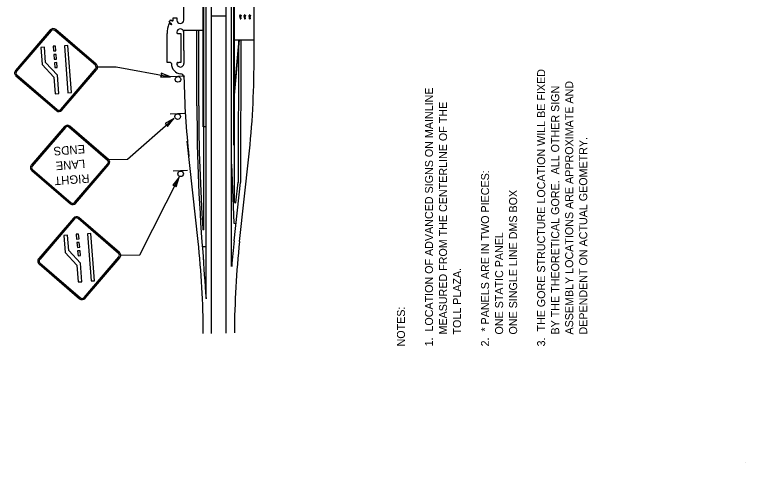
# Model space of a CAD drawing. Extents: x -102308 to -98250, y 54554 to 62383.
# Drawn here: x -101443 to -98250, y 54554 to 56510 of the extents above; entities that cross this region are included whole.
import ezdxf

# ---------------------------------------------------------------- set-up
doc = ezdxf.new("R2010")
doc.units = 0
for name, color, linetype in [('AdhocPoint_dp', 7, 'Continuous'), ('LeaderLine_dp', 7, 'Continuous'), ('RoadwayMisc', 7, 'Continuous'), ('SignPanel', 7, 'Continuous'), ('SignSupport', 7, 'Continuous'), ('TextNotes', 7, 'Continuous')]:
    doc.layers.add(name, color=color, linetype=linetype)

msp = doc.modelspace()

# ---------------------------------------------------------------- linework, layer by layer
at = {"layer": 'AdhocPoint_dp'}
msp.add_line((-98250.2, 54553.9), (-98250.2, 54553.9), dxfattribs=at)
at = {"layer": 'LeaderLine_dp'}
for p, q in [((-101082.8, 56281.7), (-100999.4, 56282.5)), ((-100999.4, 56282.5), (-100761.4, 56238.2)), ((-100800.9, 56245.5), (-100805.6, 56238.2)), ((-100805.6, 56238.2), (-100761.4, 56238.2)), ((-100761.4, 56238.2), (-100802.6, 56254.4)), ((-100802.6, 56254.4), (-100800.9, 56245.5)), ((-100949.7, 55878.4), (-100747.2, 56056.5)), ((-100747.2, 56056.5), (-100785.4, 56034.1)), ((-100774.5, 56021.7), (-100747.2, 56056.5)), ((-100785.4, 56034.1), (-100777.4, 56030)), ((-100777.4, 56030), (-100774.5, 56021.7)), ((-101033.1, 55877.6), (-100949.7, 55878.4)), ((-100896.3, 55460.1), (-100724.4, 55800.5)), ((-100724.4, 55800.5), (-100751.5, 55765.5)), ((-100736.8, 55758), (-100724.4, 55800.5)), ((-100751.5, 55765.5), (-100742.5, 55764.6)), ((-100742.5, 55764.6), (-100736.8, 55758)), ((-100979.6, 55459.3), (-100896.3, 55460.1))]:
    msp.add_line(p, q, dxfattribs=at)
at = {"layer": 'RoadwayMisc'}
for p, q in [((-100582.8, 55117.4), (-100582.8, 62374)), ((-100518.8, 55119.1), (-100518.8, 62374)), ((-100494.8, 55409.7), (-100494.8, 57849.7)), ((-100484.8, 55939.6), (-100484.8, 57219.6)), ((-100482.8, 55689), (-100482.8, 57219.6)), ((-100618.8, 56019.6), (-100618.8, 57119.6)), ((-100616.8, 56019.6), (-100616.8, 57119.6)), ((-100606.8, 56019.6), (-100606.8, 57119.6)), ((-100704.4, 56486.1), (-100704.4, 56804.6)), ((-100397.1, 56304.6), (-100397.1, 56804.6)), ((-100749.7, 56485.6), (-100749.7, 56496.9)), ((-100749.7, 56496.9), (-100749.7, 56496.9)), ((-100749.7, 56496.9), (-100733.7, 56496.9)), ((-100733.7, 56496.9), (-100733.7, 56496.9)), ((-100733.7, 56496.9), (-100733.7, 56486.1)), ((-100582.8, 56504.6), (-100518.8, 56504.6)), ((-100459.6, 56508), (-100452.8, 56508)), ((-100459.6, 56508), (-100459.6, 56506)), ((-100457.2, 56496), (-100459.6, 56506)), ((-100457.8, 56509.6), (-100458.8, 56509.6)), ((-100458.8, 56509.6), (-100458.8, 56508.6)), ((-100458.8, 56508.6), (-100457.8, 56508.6)), ((-100458.2, 56496), (-100458.2, 56492.5)), ((-100458.2, 56496), (-100457.2, 56496)), ((-100457.8, 56508.6), (-100457.8, 56509.6)), ((-100457.2, 56496), (-100457.2, 56492.5)), ((-100457.2, 56496), (-100455.2, 56496)), ((-100457.2, 56492.5), (-100455.2, 56492.5)), ((-100455.2, 56496), (-100452.8, 56506)), ((-100455.2, 56496), (-100455.2, 56492.5)), ((-100454.2, 56496), (-100455.2, 56496)), ((-100454.2, 56496), (-100454.2, 56492.5)), ((-100452.8, 56508), (-100452.8, 56506)), ((-100440.8, 56508), (-100434, 56508)), ((-100440.8, 56508), (-100440.8, 56506)), ((-100438.4, 56496), (-100440.8, 56506)), ((-100439, 56509.6), (-100440, 56509.6)), ((-100440, 56509.6), (-100440, 56508.6)), ((-100440, 56508.6), (-100439, 56508.6)), ((-100439.4, 56496), (-100438.4, 56496)), ((-100439.4, 56496), (-100439.4, 56492.5)), ((-100439, 56508.6), (-100439, 56509.6)), ((-100438.4, 56496), (-100438.4, 56492.5)), ((-100438.4, 56496), (-100436.4, 56496)), ((-100438.4, 56492.5), (-100436.4, 56492.5)), ((-100436.4, 56496), (-100434, 56506)), ((-100436.4, 56496), (-100436.4, 56492.5)), ((-100435.4, 56496), (-100436.4, 56496)), ((-100435.4, 56496), (-100435.4, 56492.5)), ((-100434, 56508), (-100434, 56506)), ((-100419, 56508), (-100412.2, 56508)), ((-100419, 56508), (-100419, 56506)), ((-100416.6, 56496), (-100419, 56506)), ((-100417.2, 56509.6), (-100418.2, 56509.6)), ((-100418.2, 56509.6), (-100418.2, 56508.6)), ((-100418.2, 56508.6), (-100417.2, 56508.6)), ((-100417.6, 56496), (-100417.6, 56492.5)), ((-100417.6, 56496), (-100416.6, 56496)), ((-100417.2, 56508.6), (-100417.2, 56509.6)), ((-100416.6, 56496), (-100416.6, 56492.5)), ((-100416.6, 56496), (-100414.6, 56496)), ((-100416.6, 56492.5), (-100414.6, 56492.5)), ((-100414.6, 56496), (-100412.2, 56506)), ((-100413.6, 56496), (-100414.6, 56496)), ((-100414.6, 56496), (-100414.6, 56492.5)), ((-100413.6, 56496), (-100413.6, 56492.5)), ((-100412.2, 56508), (-100412.2, 56506)), ((-100704.4, 56353.3), (-100704.4, 56441)), ((-100618.8, 56441), (-100704.4, 56441)), ((-100646.7, 56111.2), (-100646.7, 56441)), ((-100638.7, 56111.2), (-100638.7, 56441)), ((-100482.8, 56400.6), (-100462.3, 56400.6)), ((-100482.8, 56180), (-100462.3, 56400.6)), ((-100482.8, 56158.3), (-100460.3, 56400.6)), ((-100464.5, 56400.7), (-100466.2, 55777.1)), ((-100460.3, 56400.6), (-100397.1, 56400.6)), ((-100454.5, 56400.7), (-100456.2, 55777)), ((-100763.4, 56301.1), (-100768.9, 56301.1)), ((-100729.4, 56301.1), (-100726.3, 56301.1)), ((-100616.8, 56019.6), (-100618.8, 56019.6)), ((-100606.8, 56019.6), (-100618.8, 56019.6)), ((-100616.8, 55570.6), (-100616.8, 56019.6)), ((-100606.8, 55269.4), (-100606.8, 56019.6)), ((-100640.9, 55519.7), (-100688.7, 55956.7)), ((-100484.7, 55939.6), (-100482.7, 55939.6)), ((-100460.2, 55519.6), (-100419.7, 55889.6)), ((-100494.8, 55857.6), (-100485.7, 55599.1)), ((-100494.8, 55840.2), (-100494.1, 55839.4)), ((-100484, 55522.2), (-100456.2, 55777)), ((-100475.9, 55688.3), (-100466.1, 55778.1)), ((-100482.8, 55689), (-100475.9, 55688.3)), ((-100485.7, 55599.1), (-100475.8, 55598)), ((-100616.8, 55570.6), (-100620.4, 55570.6)), ((-100606.8, 55495.6), (-100623, 55495.6))]:
    msp.add_line(p, q, dxfattribs=at)
for points in [[(-100757.2, 56469), (-100767.9, 56477), (-100767.9, 56477), (-100760, 56487.4), (-100760, 56487.4), (-100754.5, 56483.2)], [(-100769.9, 56470.8), (-100758.1, 56467.2)], [(-100776.4, 56301.1), (-100776.4, 56301.1), (-100776.4, 56427.1)], [(-100729.7, 56427.1), (-100716.4, 56427.1), (-100716.4, 56301.1), (-100726.3, 56301.1)], [(-100768.9, 56301.1), (-100776.4, 56301.1)]]:
    msp.add_lwpolyline(points, dxfattribs=at)
for centre, radius, start, end in [((-100752.7, 56485.6), 3, 233.0709, 0.0008), ((-100718.7, 56486.1), 15, 180, 267.2045), ((-100719.4, 56486.1), 15, 269.9986, 359.9981), ((-100626.4, 56427.1), 150, 163.0703, 179.9985), ((-100757.8, 56468.2), 1, 253.0525, 53.063), ((-100729.7, 56432.1), 5, 160.5302, 270), ((-100719.4, 56432.7), 15, 359.9989, 176.5954), ((-98794.4, 56353.2), 1910, 179.9968, 181.7147), ((-100763.4, 56296.1), 5, 359.9881, 89.9954), ((-100714.4, 56296.1), 44, 179.995, 265.6625), ((-100729.4, 56296.1), 5, 89.9925, 179.9951), ((-100719, 56296.6), 15.4, 181.7192, 1.7209), ((-96884.7, 56304.6), 3819.2, 180, 180.1138), ((-104216.8, 56304.6), 3819.7, 353.7628, 360), ((-100718.8, 56237.3), 15, 1.0063, 85.6625), ((-96884.7, 56304.6), 3819.2, 181.0063, 186.2372), ((-92646.7, 56111.2), 8000, 179.99992, 184.87894), ((-92646.7, 56111.2), 7992, 179.99992, 183.87996), ((-104438.5, 55104.6), 3819.7, 0.1778, 6.2372), ((-96663.1, 55104.6), 3843.7, 173.7628, 175.4472), ((-96663.1, 55104.6), 3819.7, 173.7628, 179.7687), ((-86274.8, 56389.3), 14375.7, 183.63987, 184.46998)]:
    msp.add_arc(centre, radius, start, end, dxfattribs=at)
at = {"layer": 'SignPanel'}
for p, q in [((-101287.2, 56443.2), (-101439.1, 56266.2)), ((-101283, 56439.6), (-101434.9, 56262.6)), ((-101090.3, 56288.9), (-101267.3, 56440.8)), ((-101086.7, 56293.1), (-101263.7, 56445)), ((-101312.6, 56367.9), (-101328.7, 56366.7)), ((-101328.7, 56366.7), (-101323.1, 56293)), ((-101307.5, 56301.2), (-101312.6, 56367.9)), ((-101264.8, 56373.1), (-101275.1, 56372.2)), ((-101275.1, 56372.2), (-101273.4, 56351.4)), ((-101263, 56352.3), (-101264.8, 56373.1)), ((-101211, 56375.7), (-101225.7, 56374.6)), ((-101225.7, 56374.6), (-101210, 56168.2)), ((-101195.3, 56169.4), (-101211, 56375.7)), ((-101273.4, 56351.4), (-101263, 56352.3)), ((-101261.7, 56336.7), (-101272.1, 56335.9)), ((-101272.1, 56335.9), (-101270.3, 56315.1)), ((-101259.9, 56316), (-101261.7, 56336.7)), ((-101323.1, 56293), (-101271.9, 56237.7)), ((-101256.3, 56245.9), (-101307.5, 56301.2)), ((-101270.3, 56315.1), (-101259.9, 56316)), ((-101258.6, 56300.4), (-101269, 56299.5)), ((-101269, 56299.5), (-101267.2, 56278.8)), ((-101256.9, 56279.7), (-101258.6, 56300.4)), ((-101267.2, 56278.8), (-101256.9, 56279.7)), ((-101241, 56096.2), (-101089.1, 56273.2)), ((-101236.8, 56092.5), (-101084.9, 56269.6)), ((-101437.4, 56242.7), (-101260.3, 56090.8)), ((-101433.7, 56246.9), (-101256.7, 56095)), ((-101271.9, 56237.7), (-101266.2, 56163.9)), ((-101250.1, 56165.2), (-101256.3, 56245.9)), ((-101266.2, 56163.9), (-101250.1, 56165.2)), ((-101210, 56168.2), (-101195.3, 56169.4)), ((-101225, 56021.2), (-101370.3, 55851.8)), ((-101220.9, 56017.8), (-101366.3, 55848.4)), ((-101036.6, 55873.5), (-101206, 56018.9)), ((-101033.1, 55877.6), (-101202.5, 56022.9)), ((-101180.8, 55689.1), (-101035.4, 55858.5)), ((-101176.8, 55685.7), (-101031.4, 55855.1)), ((-101368.6, 55829.3), (-101199.2, 55684)), ((-101365.2, 55833.4), (-101195.8, 55688)), ((-100985.5, 55471.4), (-101162.5, 55623.4)), ((-101186, 55621.6), (-101338, 55444.5)), ((-101181.8, 55617.9), (-101333.7, 55440.9)), ((-100989.1, 55467.2), (-101166.1, 55619.1)), ((-101211.4, 55546.3), (-101227.5, 55545)), ((-101227.5, 55545), (-101221.9, 55471.3)), ((-101206.3, 55479.5), (-101211.4, 55546.3)), ((-101163.6, 55551.4), (-101174, 55550.5)), ((-101174, 55550.5), (-101172.2, 55529.7)), ((-101172.2, 55529.7), (-101161.8, 55530.6)), ((-101161.8, 55530.6), (-101163.6, 55551.4)), ((-101109.8, 55554), (-101124.6, 55552.9)), ((-101124.6, 55552.9), (-101108.8, 55346.6)), ((-101094.1, 55347.7), (-101109.8, 55554)), ((-101160.5, 55515), (-101170.9, 55514.2)), ((-101170.9, 55514.2), (-101169.1, 55493.4)), ((-101169.1, 55493.4), (-101158.7, 55494.3)), ((-101158.7, 55494.3), (-101160.5, 55515)), ((-101221.9, 55471.3), (-101170.7, 55416)), ((-101155.1, 55424.2), (-101206.3, 55479.5)), ((-101157.4, 55478.7), (-101167.8, 55477.8)), ((-101167.8, 55477.8), (-101166.1, 55457.1)), ((-101155.7, 55458), (-101157.4, 55478.7)), ((-101166.1, 55457.1), (-101155.7, 55458)), ((-101139.8, 55274.5), (-100987.9, 55451.5)), ((-101135.6, 55270.9), (-100983.7, 55447.9)), ((-101336.2, 55421), (-101159.1, 55269.1)), ((-101332.5, 55425.2), (-101155.5, 55273.3)), ((-101170.7, 55416), (-101165.1, 55342.3)), ((-101148.9, 55343.5), (-101155.1, 55424.2)), ((-101165.1, 55342.3), (-101148.9, 55343.5)), ((-101108.8, 55346.6), (-101094.1, 55347.7))]:
    msp.add_line(p, q, dxfattribs=at)
for centre, radius, start, end in [((-101274.6, 56432.4), 16.7, 49.3622, 139.3622), ((-101274.6, 56432.4), 11.1, 49.3622, 139.3622), ((-101097.5, 56280.4), 16.7, 319.3622, 49.3622), ((-101426.5, 56255.3), 16.7, 139.3622, 229.3622), ((-101426.5, 56255.3), 11.1, 139.3622, 229.3622), ((-101097.5, 56280.4), 11.1, 319.3622, 49.3622), ((-101249.5, 56103.4), 16.7, 229.3622, 319.3622), ((-101249.5, 56103.4), 11.1, 229.3622, 319.3622), ((-101212.9, 56010.8), 15.9, 49.3622, 139.3622), ((-101212.9, 56010.8), 10.6, 49.3622, 139.3622), ((-101043.5, 55865.5), 15.9, 319.3622, 49.3622), ((-101358.2, 55841.4), 15.9, 139.3622, 229.3622), ((-101358.2, 55841.4), 10.6, 139.3622, 229.3622), ((-101043.5, 55865.5), 10.6, 319.3622, 49.3622), ((-101188.9, 55696.1), 10.6, 229.3622, 319.3622), ((-101188.9, 55696.1), 15.9, 229.3622, 319.3622), ((-101173.4, 55610.7), 16.7, 49.3622, 139.3622), ((-101173.4, 55610.7), 11.1, 49.3622, 139.3622), ((-100996.3, 55458.8), 11.1, 319.3622, 49.3622), ((-100996.3, 55458.8), 16.7, 319.3622, 49.3622), ((-101325.3, 55433.7), 16.7, 139.3622, 229.3622), ((-101325.3, 55433.7), 11.1, 139.3622, 229.3622), ((-101148.3, 55281.7), 16.7, 229.3622, 319.3622), ((-101148.3, 55281.7), 11.1, 229.3622, 319.3622)]:
    msp.add_arc(centre, radius, start, end, dxfattribs=at)
at = {"layer": 'SignSupport'}
for p, q in [((-100699.8, 56241.4), (-100761.4, 56238.2)), ((-100701.2, 56078.8), (-100762.8, 56075.5)), ((-100688.1, 55828.9), (-100749.7, 55825.6))]:
    msp.add_line(p, q, dxfattribs=at)
for centre in [(-100729.6, 56227.2), (-100731, 56064.6), (-100717.9, 55814.7)]:
    msp.add_circle(centre, 12.2, dxfattribs=at)

# ---------------------------------------------------------------- texts
at = {"layer": 'SignPanel'}
for s, p in [('ENDS', (-101136.9, 55941.8)), ('LANE', (-101136.3, 55876.9)), ('RIGHT', (-101117.7, 55813.4))]:
    msp.add_text(s, height=36.99, rotation=184.3622, dxfattribs=at).set_placement(p)
at = {"layer": 'TextNotes'}
for s, p in [('3.  THE GORE STRUCTURE LOCATION WILL BE FIXED', (-99125.1, 55060.5)), ('    ASSEMBLY LOCATIONS ARE APPROXIMATE AND', (-99002.6, 55060.5)), ('1.  LOCATION OF ADVANCED SIGNS ON MAINLINE ', (-99615.1, 55060.5)), ('    BY THE THEORETICAL GORE.  ALL OTHER SIGN', (-99063.8, 55060.5)), ('    MEASURED FROM THE CENTERLINE OF THE', (-99553.8, 55060.5)), ('    DEPENDENT ON ACTUAL GEOMETRY.', (-98941.3, 55060.5)), ('2.  * PANELS ARE IN TWO PIECES:', (-99370.1, 55060.5)), ('    ONE SINGLE LINE DMS BOX', (-99247.6, 55060.5)), ('    ONE STATIC PANEL', (-99308.8, 55060.5)), ('    TOLL PLAZA.', (-99492.6, 55060.5)), ('NOTES:', (-99737.6, 55060.5))]:
    msp.add_text(s, height=35, rotation=90, dxfattribs=at).set_placement(p)

doc.saveas('drawing.dxf')
